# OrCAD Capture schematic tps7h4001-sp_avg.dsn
size Custom
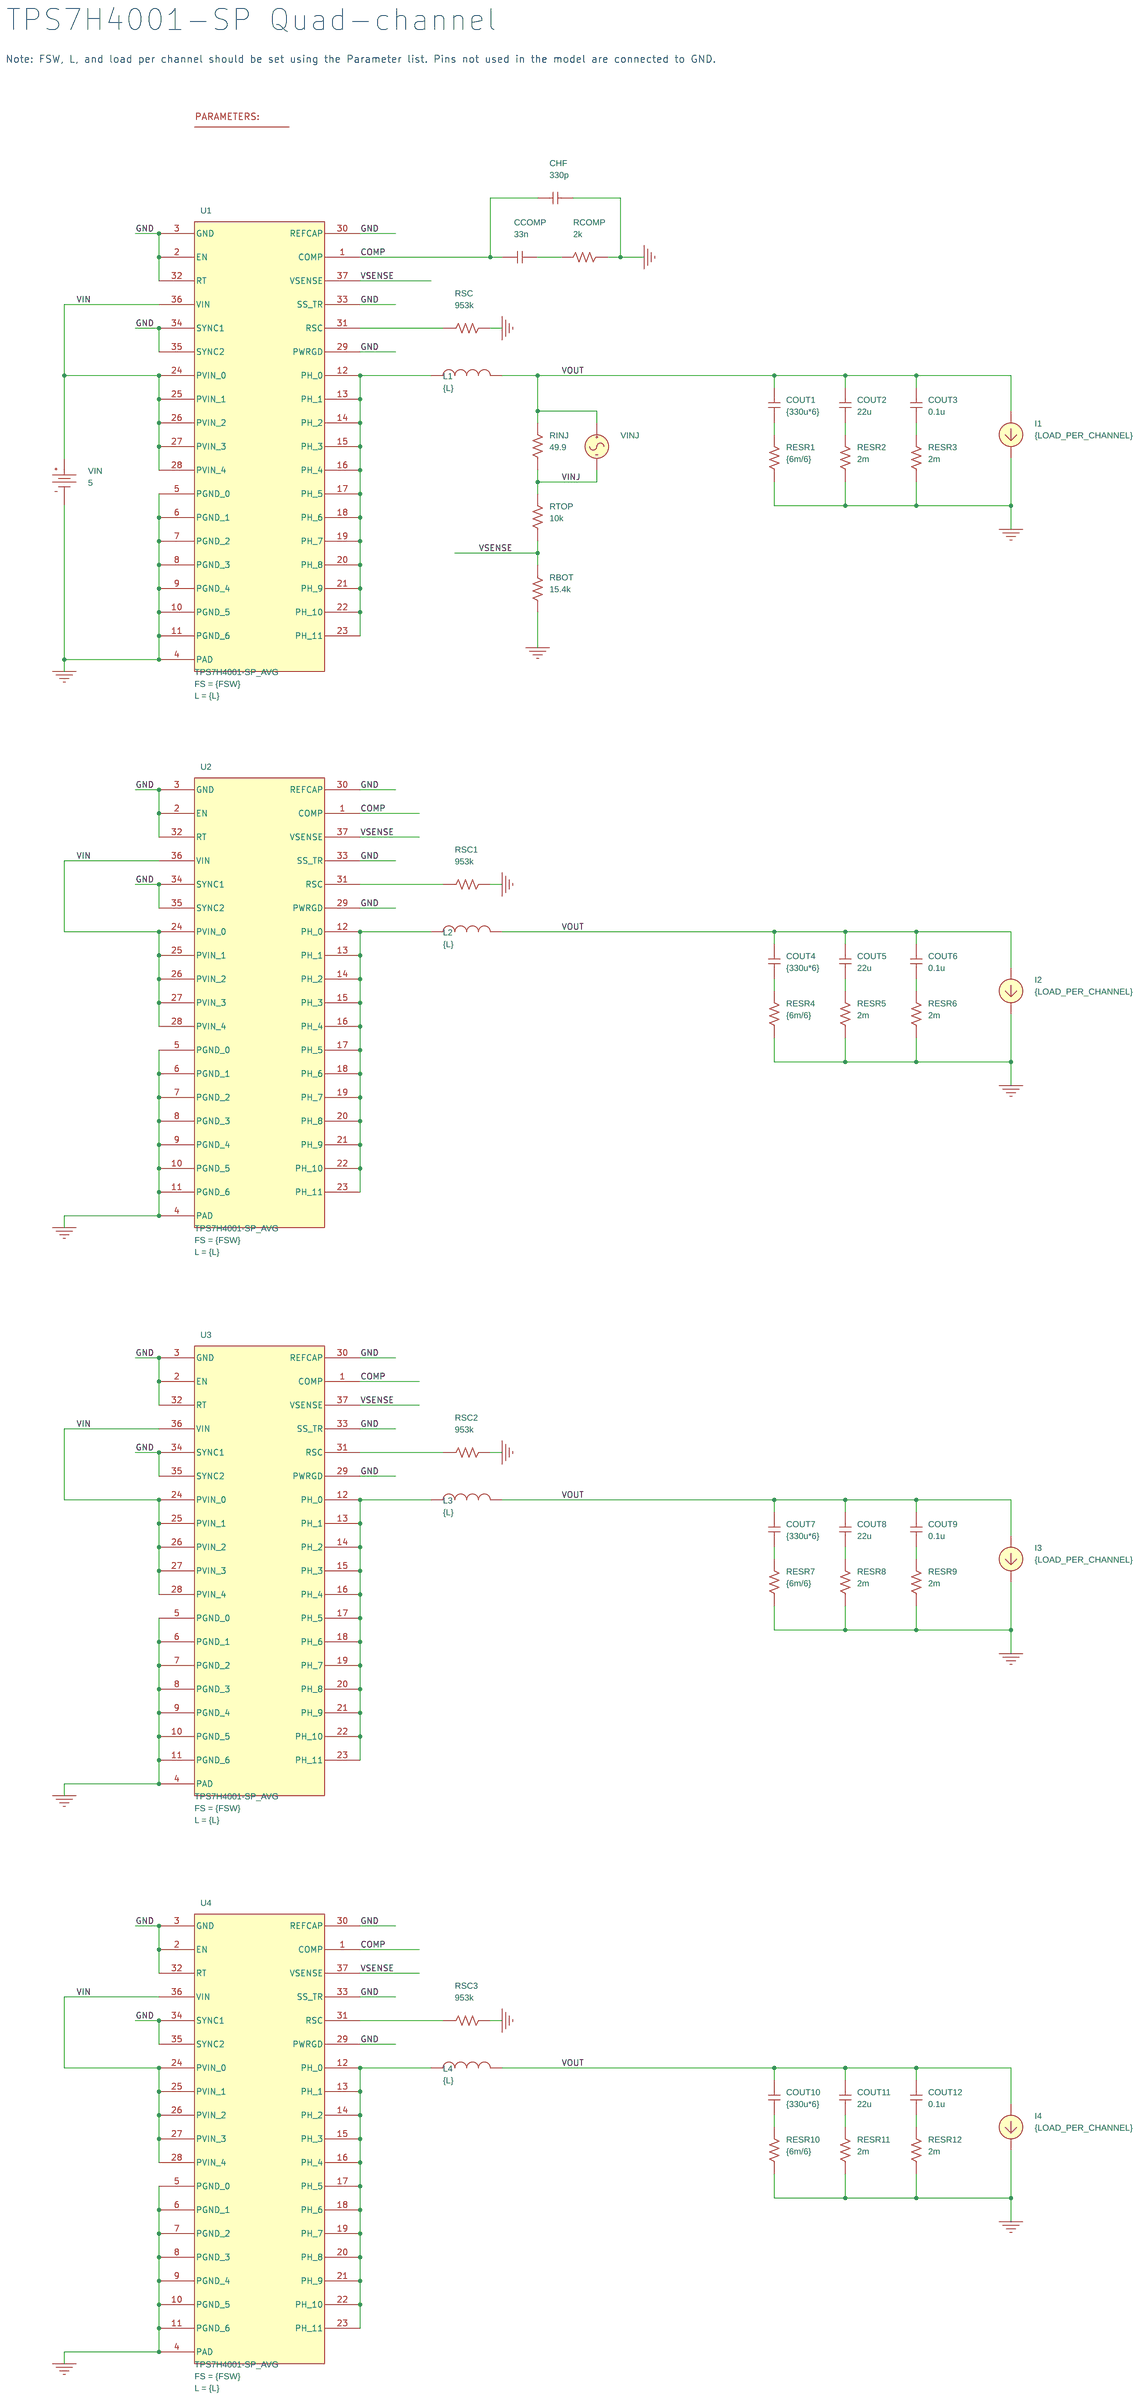
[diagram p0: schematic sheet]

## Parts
1  PARAM
CCOMP  33n  [RAD/CK05]
CHF  330p  [RAD/CK05]
COUT1  {330u*6}  [RAD/CK05]
COUT2  22u  [RAD/CK05]
COUT3  0.1u  [RAD/CK05]
COUT4  {330u*6}  [RAD/CK05]
COUT5  22u  [RAD/CK05]
COUT6  0.1u  [RAD/CK05]
COUT7  {330u*6}  [RAD/CK05]
COUT8  22u  [RAD/CK05]
COUT9  0.1u  [RAD/CK05]
COUT10  {330u*6}  [RAD/CK05]
COUT11  22u  [RAD/CK05]
COUT12  0.1u  [RAD/CK05]
I1  IDC
I2  IDC
I3  IDC
I4  IDC
L1  {L}  [DISC/.350x.175/LS.200x.100/.034]
L2  {L}  [DISC/.350x.175/LS.200x.100/.034]
L3  {L}  [DISC/.350x.175/LS.200x.100/.034]
L4  {L}  [DISC/.350x.175/LS.200x.100/.034]
RBOT  15.4k  [AX/RC05]
RCOMP  2k  [AX/RC05]
RESR1  {6m/6}  [AX/RC05]
RESR2  2m  [AX/RC05]
RESR3  2m  [AX/RC05]
RESR4  {6m/6}  [AX/RC05]
RESR5  2m  [AX/RC05]
RESR6  2m  [AX/RC05]
RESR7  {6m/6}  [AX/RC05]
RESR8  2m  [AX/RC05]
RESR9  2m  [AX/RC05]
RESR10  {6m/6}  [AX/RC05]
RESR11  2m  [AX/RC05]
RESR12  2m  [AX/RC05]
RINJ  49.9  [AX/RC05]
RSC  953k  [AX/RC05]
RSC1  953k  [AX/RC05]
RSC2  953k  [AX/RC05]
RSC3  953k  [AX/RC05]
RTOP  10k  [AX/RC05]
U1  TPS7H4001-SP_AVG
U2  TPS7H4001-SP_AVG
U3  TPS7H4001-SP_AVG
U4  TPS7H4001-SP_AVG
VIN  VDC
VINJ  VAC

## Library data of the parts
1 = PARAM: FSW: 500k; L: 0.9u; LOAD_PER_CHANNEL: 16.75
CCOMP CHF COUT1-COUT12 = C
I1-I4 = IDC: DC: {LOAD_PER_CHANNEL}
L1-L4 = L_v2
RBOT RCOMP RESR1-RESR12 RINJ RSC RSC1-RSC3 RTOP = R
U1-U4 = TPS7H4001-SP_AVG: FS: {FSW}; L: {L}
VIN = VDC: DC: 5
VINJ = VAC

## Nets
GND: U1.2(EN) U1.3(GND) U1.29(PWRGD) U1.30(REFCAP) U1.32(RT) U1.33(SS_TR) U1.34(SYNC1) U1.35(SYNC2) U2.2(EN) U2.3(GND) U2.29(PWRGD) U2.30(REFCAP) U2.32(RT) U2.33(SS_TR) U2.34(SYNC1) U2.35(SYNC2) U3.2(EN) U3.3(GND) U3.29(PWRGD) U3.30(REFCAP) U3.32(RT) U3.33(SS_TR) U3.34(SYNC1) U3.35(SYNC2) U4.2(EN) U4.3(GND) U4.29(PWRGD) U4.30(REFCAP) U4.32(RT) U4.33(SS_TR) U4.34(SYNC1) U4.35(SYNC2)
VIN: U1.24(PVIN_0) U1.25(PVIN_1) U1.26(PVIN_2) U1.27(PVIN_3) U1.28(PVIN_4) U1.36(VIN) U2.24(PVIN_0) U2.25(PVIN_1) U2.26(PVIN_2) U2.27(PVIN_3) U2.28(PVIN_4) U2.36(VIN) U3.24(PVIN_0) U3.25(PVIN_1) U3.26(PVIN_2) U3.27(PVIN_3) U3.28(PVIN_4) U3.36(VIN) U4.24(PVIN_0) U4.25(PVIN_1) U4.26(PVIN_2) U4.27(PVIN_3) U4.28(PVIN_4) U4.36(VIN) VIN.0(+)
VINJ: RINJ.1 RTOP.2 VINJ.2(-)
0: CHF.2 I1.2(-) I2.2(-) I3.2(-) I4.2(-) RBOT.2 RCOMP.1 RESR1.1 RESR2.1 RESR3.1 RESR4.1 RESR5.1 RESR6.1 RESR7.1 RESR8.1 RESR9.1 RESR10.1 RESR11.1 RESR12.1 RSC.2 RSC1.2 RSC2.2 RSC3.2 U1.4(PAD) U1.5(PGND_0) U1.6(PGND_1) U1.7(PGND_2) U1.8(PGND_3) U1.9(PGND_4) U1.10(PGND_5) U1.11(PGND_6) U2.4(PAD) U2.5(PGND_0) U2.6(PGND_1) U2.7(PGND_2) U2.8(PGND_3) U2.9(PGND_4) U2.10(PGND_5) U2.11(PGND_6) U3.4(PAD) U3.5(PGND_0) U3.6(PGND_1) U3.7(PGND_2) U3.8(PGND_3) U3.9(PGND_4) U3.10(PGND_5) U3.11(PGND_6) U4.4(PAD) U4.5(PGND_0) U4.6(PGND_1) U4.7(PGND_2) U4.8(PGND_3) U4.9(PGND_4) U4.10(PGND_5) U4.11(PGND_6) VIN.1(-)
COMP: CCOMP.1 CHF.1 U1.1(COMP) U2.1(COMP) U3.1(COMP) U4.1(COMP)
VOUT: COUT1.1 COUT2.1 COUT3.1 COUT4.1 COUT5.1 COUT6.1 COUT7.1 COUT8.1 COUT9.1 COUT10.1 COUT11.1 COUT12.1 I1.1(+) I2.1(+) I3.1(+) I4.1(+) L1.2 L2.2 L3.2 L4.2 RINJ.2 VINJ.1(+)
VSENSE: RBOT.1 RTOP.1 U1.37(VSENSE) U2.37(VSENSE) U3.37(VSENSE) U4.37(VSENSE)
N16793632: CCOMP.2 RCOMP.2
N16793677: RSC.1 U1.31(RSC)
N16793706: L1.1 U1.12(PH_0) U1.13(PH_1) U1.14(PH_2) U1.15(PH_3) U1.16(PH_4) U1.17(PH_5) U1.18(PH_6) U1.19(PH_7) U1.20(PH_8) U1.21(PH_9) U1.22(PH_10) U1.23(PH_11)
N16793772: COUT1.2 RESR1.2
N16793774: COUT2.2 RESR2.2
N16793776: COUT3.2 RESR3.2
N16794101: RSC1.1 U2.31(RSC)
N16794126: L2.1 U2.12(PH_0) U2.13(PH_1) U2.14(PH_2) U2.15(PH_3) U2.16(PH_4) U2.17(PH_5) U2.18(PH_6) U2.19(PH_7) U2.20(PH_8) U2.21(PH_9) U2.22(PH_10) U2.23(PH_11)
N16794185: COUT4.2 RESR4.2
N16794187: COUT5.2 RESR5.2
N16794189: COUT6.2 RESR6.2
N16794433: RSC2.1 U3.31(RSC)
N16794459: L3.1 U3.12(PH_0) U3.13(PH_1) U3.14(PH_2) U3.15(PH_3) U3.16(PH_4) U3.17(PH_5) U3.18(PH_6) U3.19(PH_7) U3.20(PH_8) U3.21(PH_9) U3.22(PH_10) U3.23(PH_11)
N16794515: COUT7.2 RESR7.2
N16794517: COUT8.2 RESR8.2
N16794519: COUT9.2 RESR9.2
N16794760: RSC3.1 U4.31(RSC)
N16794785: L4.1 U4.12(PH_0) U4.13(PH_1) U4.14(PH_2) U4.15(PH_3) U4.16(PH_4) U4.17(PH_5) U4.18(PH_6) U4.19(PH_7) U4.20(PH_8) U4.21(PH_9) U4.22(PH_10) U4.23(PH_11)
N16794841: COUT10.2 RESR10.2
N16794843: COUT11.2 RESR11.2
N16794845: COUT12.2 RESR12.2

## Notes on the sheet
- TPS7H4001-SP Quad-channel
- Note: FSW, L, and load per channel should be set using the Parameter list. Pins not used in the model are connected to GND.
